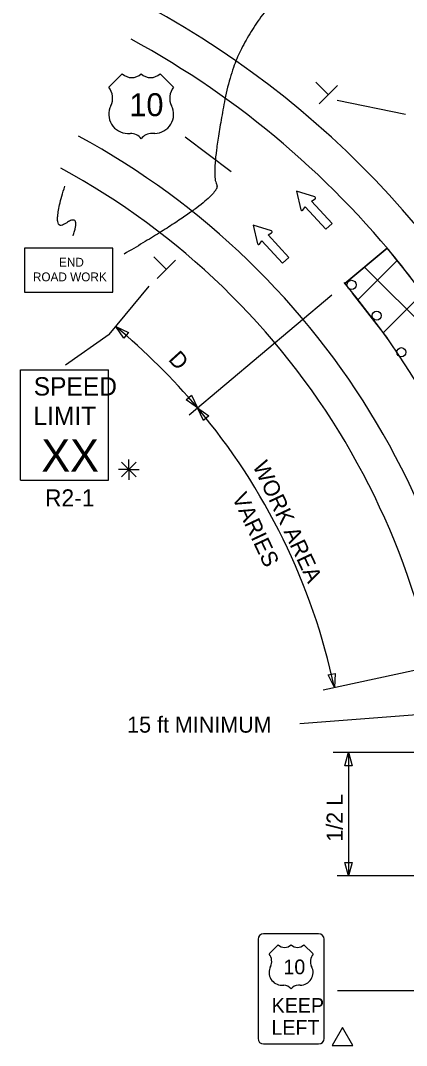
# Model space of a CAD drawing. Extents: x 16552 to 19508, y 5713 to 7079.
# Drawn here: x 16729 to 16897.2, y 6286.3 to 6732.8 of the extents above; entities that cross this region are included whole.
import ezdxf

# ---------------------------------------------------------------- set-up
doc = ezdxf.new("R2010")
doc.units = 0
for name, color, linetype in [('ALI_LEGAL_EX', 7, 'Continuous'), ('MT_SCRATCH_LEVEL_A', 7, 'Continuous'), ('MT_SCRATCH_LEVEL_E', 7, 'Continuous'), ('PAVT_EDGE_EX', 7, 'Continuous'), ('TRAFFIC_SIGNS_PR', 7, 'Continuous'), ('TYPICAL_EX', 7, 'Continuous'), ('TYPICAL_TEXT_DIMEN_PR', 7, 'Continuous')]:
    doc.layers.add(name, color=color, linetype=linetype)

msp = doc.modelspace()

# ---------------------------------------------------------------- linework, layer by layer
at = {"layer": 'ALI_LEGAL_EX'}
for points in [[(16820.7, 6666.97), (16800.68, 6681.95)], [(16888.99, 6594.32), (16873.66, 6614.07)]]:
    msp.add_lwpolyline(points, dxfattribs=at)
for centre, end in [((16629.65, 6525.15), 57.2958), ((16591.93, 6383.76), 40.1909)]:
    msp.add_arc(centre, 364, 0, end, dxfattribs=at)
at = {"layer": 'MT_SCRATCH_LEVEL_A'}
for p, q in [((16870.35, 6618.23), (16888.71, 6633.69)), ((16876.07, 6611.27), (16893.14, 6628.34)), ((16929.73, 6574.64), (16878.92, 6625.45)), ((16887.07, 6596.81), (16904.25, 6613.99))]:
    msp.add_line(p, q, dxfattribs=at)
msp.add_lwpolyline([(16888.71, 6633.69), (16888.71, 6633.69), (16870.35, 6618.23)], dxfattribs=at)
msp.add_arc((16591.93, 6383.76), 388, 28.2673, 40.102, dxfattribs=at)
at = {"layer": 'MT_SCRATCH_LEVEL_E'}
for p, q in [((16857.2, 6656), (16849.25, 6658.53)), ((16849.25, 6658.53), (16851.12, 6650.42)), ((16855.79, 6654.2), (16857.31, 6655.18)), ((16864.75, 6644.44), (16855.79, 6654.2)), ((16851.94, 6650.24), (16853.03, 6651.67)), ((16853.03, 6651.67), (16862, 6641.91)), ((16838.3, 6641.21), (16830.35, 6643.74)), ((16830.35, 6643.74), (16832.22, 6635.62)), ((16836.89, 6639.41), (16838.41, 6640.38)), ((16862, 6641.91), (16864.75, 6644.44)), ((16833.04, 6635.44), (16834.14, 6636.88)), ((16834.14, 6636.88), (16843.1, 6627.11)), ((16845.86, 6629.64), (16836.89, 6639.41)), ((16843.1, 6627.11), (16845.86, 6629.64))]:
    msp.add_line(p, q, dxfattribs=at)
for centre, start, end in [((16857.05, 6655.56), 302.594, 72.331), ((16851.57, 6650.53), 192.9827, 322.5217), ((16838.15, 6640.76), 302.594, 72.331), ((16832.67, 6635.73), 192.9827, 322.5217)]:
    msp.add_arc(centre, 0.463, start, end, dxfattribs=at)
at = {"layer": 'PAVT_EDGE_EX'}
for radius, start in [(404, 21.0961), (388, 14.0482), (340, 0), (324, 0)]:
    msp.add_arc((16591.93, 6383.76), radius, start, 61.4862, dxfattribs=at)
at = {"layer": 'TRAFFIC_SIGNS_PR'}
for p, q in [((16728.95, 6580.59), (16767.35, 6580.59)), ((16728.95, 6532.59), (16728.95, 6580.59)), ((16767.35, 6532.59), (16767.35, 6580.59)), ((16728.95, 6532.59), (16767.35, 6532.59)), ((16832.47, 6332.57), (16832.47, 6289.36)), ((16858.87, 6334.97), (16834.87, 6334.97)), ((16861.27, 6289.36), (16861.27, 6332.57)), ((16834.87, 6286.97), (16858.87, 6286.97))]:
    msp.add_line(p, q, dxfattribs=at)
msp.add_lwpolyline([(16730.76, 6614.5), (16769.16, 6614.5), (16769.16, 6633.7), (16730.76, 6633.7)], close=True, dxfattribs=at)
for centre in [(16873.23, 6617.66), (16884.19, 6604.26), (16894.93, 6588.32)]:
    msp.add_circle(centre, 2, dxfattribs=at)
for centre, start, end in [((16834.87, 6332.57), 90, 180), ((16858.87, 6332.57), 0, 90), ((16834.87, 6289.37), 180, 270), ((16858.87, 6289.37), 270, 0)]:
    msp.add_arc(centre, 2.4, start, end, dxfattribs=at)
at = {"layer": 'TYPICAL_EX'}
for p, q in [((16767.4, 6703.75), (16773.29, 6709.64)), ((16795.7, 6703.75), (16789.8, 6709.64)), ((16775.64, 6683.69), (16776.82, 6683.69)), ((16787.45, 6683.69), (16786.27, 6683.69)), ((16837.27, 6326.17), (16841.27, 6330.17)), ((16856.47, 6326.17), (16852.47, 6330.17)), ((16842.87, 6312.56), (16843.67, 6312.56)), ((16850.88, 6312.56), (16850.08, 6312.56))]:
    msp.add_line(p, q, dxfattribs=at)
for centre, radius, start, end in [((16777.42, 6713.94), 5.96, 226.1404, 313.8596), ((16785.67, 6713.94), 5.96, 226.1404, 313.8596), ((16761.81, 6699.03), 7.31, 333.0977, 40.1936), ((16801.28, 6699.03), 7.31, 139.8064, 206.9023), ((16775.66, 6691.93), 8.24, 152.6698, 269.9013), ((16787.43, 6691.93), 8.24, 270.0987, 27.3302), ((16776.84, 6677.78), 5.91, 37.1038, 90.1385), ((16786.26, 6677.78), 5.91, 89.8615, 142.8962), ((16844.07, 6333.08), 4.04, 226.1404, 313.8596), ((16849.67, 6333.08), 4.04, 226.1404, 313.8596), ((16833.48, 6322.96), 4.96, 333.0977, 40.1936), ((16860.26, 6322.96), 4.96, 139.8064, 206.9023), ((16842.88, 6318.15), 5.59, 152.6698, 269.9013), ((16850.87, 6318.15), 5.59, 270.0987, 27.3302), ((16843.68, 6308.55), 4.01, 37.1038, 90.1385), ((16850.07, 6308.55), 4.01, 89.8615, 142.8962)]:
    msp.add_arc(centre, radius, start, end, dxfattribs=at)
at = {"layer": 'TYPICAL_TEXT_DIMEN_PR'}
for p, q in [((16863.11, 6700.49), (16857.59, 6705.99)), ((16867.08, 6704.48), (16859.14, 6696.51)), ((16866.93, 6698.15), (16896.78, 6692.02)), ((16792.55, 6624.4), (16787.03, 6629.9)), ((16796.52, 6628.39), (16788.58, 6620.42)), ((16767.65, 6596.08), (16785.02, 6617.08)), ((16802.5, 6561.09), (16864.56, 6613.35)), ((16767.65, 6596.08), (16748.52, 6582.69)), ((16773.97, 6594.52), (16770.45, 6599.47)), ((16770.45, 6599.47), (16775.97, 6596.94)), ((16774.97, 6595.73), (16773.97, 6594.52)), ((16775.97, 6596.94), (16774.97, 6595.73)), ((16801.12, 6567.6), (16802.33, 6568.61)), ((16802.33, 6568.61), (16803.53, 6569.62)), ((16803.53, 6569.62), (16806.1, 6564.12)), ((16806.1, 6564.12), (16801.12, 6567.6)), ((16808.68, 6558.63), (16806.1, 6564.12)), ((16806.1, 6564.12), (16811.08, 6560.65)), ((16811.08, 6560.65), (16809.88, 6559.64)), ((16809.88, 6559.64), (16808.68, 6558.63)), ((16779.33, 6540.4), (16772.95, 6534.02)), ((16772.96, 6540.4), (16779.33, 6534.02)), ((16776.14, 6537.21), (16776.14, 6541.66)), ((16776.14, 6537.21), (16771.61, 6537.21)), ((16776.14, 6537.21), (16779.33, 6537.21)), ((16776.14, 6537.21), (16780.62, 6537.21)), ((16776.14, 6537.21), (16776.14, 6532.71)), ((16860.85, 6441.29), (16944.94, 6459.28)), ((16862.97, 6447.74), (16864.51, 6448.07)), ((16864.51, 6448.07), (16866.05, 6448.4)), ((16866.05, 6448.4), (16865.74, 6442.33)), ((16865.74, 6442.33), (16862.97, 6447.74)), ((16935.91, 6433.02), (16850.71, 6426.47)), ((16865.26, 6414.06), (16925.83, 6414.06)), ((16870.36, 6408.2), (16871.93, 6414.06)), ((16871.93, 6414.06), (16871.93, 6360.21)), ((16871.93, 6414.06), (16873.5, 6408.2)), ((16871.93, 6408.2), (16870.36, 6408.2)), ((16873.5, 6408.2), (16871.93, 6408.2)), ((16871.93, 6360.21), (16870.36, 6366.07)), ((16870.36, 6366.07), (16871.93, 6366.07)), ((16871.93, 6366.07), (16873.5, 6366.07)), ((16873.5, 6366.07), (16871.93, 6360.21)), ((16970.82, 6360.21), (16866.93, 6360.21)), ((16867.03, 6310.21), (16952.43, 6310.21))]:
    msp.add_line(p, q, dxfattribs=at)
msp.add_lwpolyline([(16869.24, 6294.14), (16864.71, 6286.31), (16873.76, 6286.31)], close=True, dxfattribs=at)
for start, end in [(40.102, 50.3886), (12.0744, 40.102)]:
    msp.add_arc((16591.93, 6383.76), 280, start, end, dxfattribs=at)
for points in [[(16869.81, 6768.82), (16825.93, 6737.09), (16811.54, 6666.42), (16817.3, 6656.33), (16774.14, 6631.09)], [(16751.84, 6639.02), (16755.44, 6649.11), (16741.77, 6639.74), (16748.25, 6660.65)]]:
    msp.add_open_spline(points, degree=2, dxfattribs=at)

# ---------------------------------------------------------------- texts
at = {"layer": 'TRAFFIC_SIGNS_PR'}
for s, height, p in [('END', 3.831, (16745.76, 6625.63)), ('ROAD WORK', 3.831, (16734.37, 6619.24)), ('SPEED', 8, (16734.72, 6569.46)), ('LIMIT', 8, (16734.56, 6556.66)), ('XX', 14.031, (16738.07, 6536.35)), ('R2-1', 7.44, (16739.63, 6521.15)), ('10', 6.4, (16843.53, 6317.36)), ('KEEP', 6.4, (16838.41, 6300.57)), ('LEFT', 6.4, (16838.32, 6290.97))]:
    msp.add_text(s, height=height, dxfattribs=at).set_placement(p)
at = {"layer": 'TYPICAL_EX'}
msp.add_text('10', height=10, dxfattribs=at).set_placement((16776.39, 6691.17))
at = {"layer": 'TYPICAL_TEXT_DIMEN_PR'}
for s, rotation, p in [('D', 312.2189, (16793.06, 6584.99)), ('WORK AREA', 295.1762, (16829.99, 6538.92)), ('VARIES', 295.1762, (16820.99, 6525.14)), ('1/2 L', 90, (16869.37, 6375.08))]:
    msp.add_text(s, height=7, rotation=rotation, dxfattribs=at).set_placement(p)
msp.add_text('15 ft MINIMUM', height=7, dxfattribs=at).set_placement((16775.45, 6422.6))

doc.saveas('drawing.dxf')
